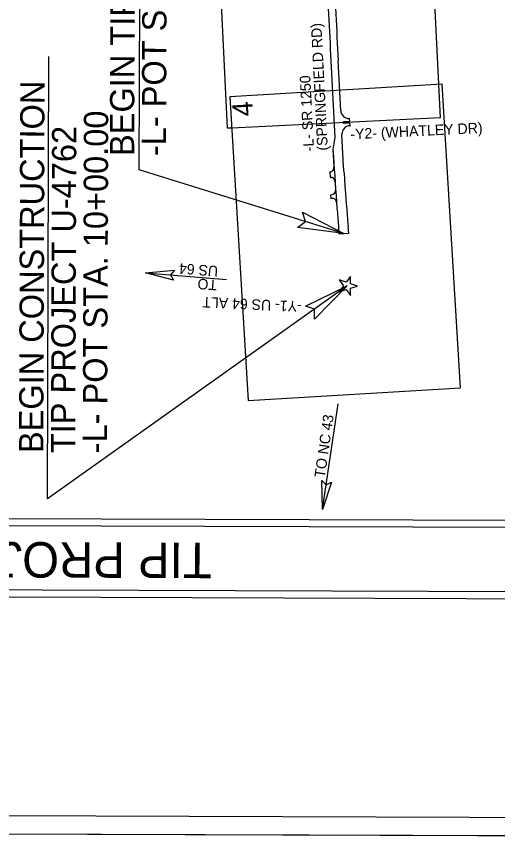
# Model space of a CAD drawing. Extents: x 2364794 to 2387902, y 795230 to 810426.
# Drawn here: x 2367330 to 2369706, y 798611 to 802661 of the extents above; entities that cross this region are included whole.
import ezdxf

# ---------------------------------------------------------------- set-up
doc = ezdxf.new("R2010")
doc.units = 0
for name, color, linetype in [('Mis Object Lines', 7, 'Continuous'), ('Old_Level_10', 7, 'Continuous'), ('Old_Level_15', 7, 'Continuous'), ('Old_Level_20', 7, 'Continuous'), ('Old_Level_21', 7, 'Continuous'), ('Old_Level_22', 7, 'Continuous'), ('Old_Level_5', 7, 'Continuous'), ('Old_Level_7', 7, 'Continuous'), ('Old_Level_8', 7, 'Continuous'), ('Plan Sheet CELL', 7, 'Continuous')]:
    doc.layers.add(name, color=color, linetype=linetype)

msp = doc.modelspace()

# ---------------------------------------------------------------- linework, layer by layer
at = {"layer": 'Mis Object Lines'}
for p, q in [((2370923.9, 800170.6), (2365078.9, 800191.3)), ((2372218.8, 800131.1), (2365078.8, 800156.3))]:
    msp.add_line(p, q, dxfattribs=at)
for points in [[(2365077.7, 799841.4), (2372217.7, 799816.1)], [(2365042.6, 799806.4), (2372252.5, 799781)], [(2365042.6, 799806.4), (2372252.5, 799781)]]:
    msp.add_lwpolyline(points, dxfattribs=at)
at = {"layer": 'Old_Level_10'}
for points in [[(2368743.3, 801694.6), (2368946.7, 801590.8), (2368718.7, 801619.8), (2368758.1, 801649.4)], [(2368106.2, 801360.1), (2367968.2, 801395.5), (2368110.9, 801409), (2368091, 801385.5)], [(2368757.7, 801232.6), (2368963.6, 801331.3), (2368802.3, 801167.7), (2368802.6, 801217)], [(2368885.9, 800364.4), (2368841.4, 800229), (2368837.4, 800372.4), (2368859.5, 800350.9)]]:
    msp.add_lwpolyline(points, close=True, dxfattribs=at)
at = {"layer": 'Old_Level_15'}
for p, q in [((2367937.1, 801904.7), (2367946.1, 804439.4)), ((2367483.3, 800281.4), (2367491, 802463.8)), ((2368946.7, 801590.8), (2367937.1, 801904.7)), ((2367968.2, 801395.5), (2368367.4, 801363.2)), ((2368963.6, 801331.3), (2367483.3, 800281.4)), ((2368841.4, 800229), (2368918.9, 800750.9))]:
    msp.add_line(p, q, dxfattribs=at)
at = {"layer": 'Old_Level_20'}
msp.add_line((2368922.7, 801589.2), (2368970.6, 801592.4), dxfattribs=at)
at = {"layer": 'Old_Level_21'}
msp.add_lwpolyline([(2364835.2, 810426.2), (2364793.5, 798638.3), (2372493.4, 798611.1), (2372535.1, 810399)], close=True, dxfattribs=at)
at = {"layer": 'Old_Level_22'}
msp.add_lwpolyline([(2372336.7, 798702.6), (2372377.9, 810368.1), (2364992.2, 810394.2), (2364951, 798728.7)], close=True, dxfattribs=at)
at = {"layer": 'Old_Level_5'}
for p, q in [((2368882.8, 802441.2), (2368902.1, 802064.1)), ((2368931.4, 802195.4), (2368918.7, 802443.1)), ((2368975.5, 802157.6), (2368973.2, 802157.5)), ((2368976.2, 802143.7), (2368975.5, 802157.6)), ((2368947.2, 802142.2), (2368976.2, 802143.7)), ((2368976.6, 802134.7), (2368947.6, 802133.4)), ((2368975.4, 802121.5), (2368977.2, 802121.6)), ((2368977.2, 802121.6), (2368976.6, 802134.7)), ((2368902.1, 802064.1), (2368893.2, 802003.6)), ((2368945.5, 801921.2), (2368937.4, 802079.5)), ((2368893.2, 802003.6), (2368897.6, 801918.7)), ((2368897.6, 801918.7), (2368897.8, 801915.9)), ((2368947.8, 801889.5), (2368945.5, 801921.2)), ((2368879.3, 801894.6), (2368878.4, 801894.5)), ((2368878.4, 801894.5), (2368879.8, 801866.8)), ((2368879.8, 801866.8), (2368881.6, 801866.9)), ((2368892.7, 801783), (2368881.4, 801779)), ((2368881.4, 801779), (2368882.5, 801761.6)), ((2368920.8, 801619), (2368922.7, 801589.2)), ((2368970.6, 801592.4), (2368968.7, 801622.5)), ((2368922.7, 801589.2), (2368970.6, 801592.4))]:
    msp.add_line(p, q, dxfattribs=at)
for centre, radius, start, end in [((2425310.1, 805339.7), 56501.7, 182.47241, 182.94048), ((2425310.1, 805339.7), 56465.7, 182.47241, 182.94048), ((2368971.4, 802197.4), 40, 182.9405, 272.6684), ((2368977.3, 802081.6), 40, 92.7637, 182.9405), ((2368947.4, 802137.8), 4.44, 92.4729, 272.8864), ((2397182.2, 803762.9), 28343.7, 183.55876, 184.08289), ((2397182.2, 803762.9), 28343.7, 183.55876, 184.08289), ((2368877.8, 801914.5), 20, 274.2541, 4.0821), ((2368882.7, 801846.9), 20, 4.1945, 93.0317), ((2377170.4, 802398.1), 8238.3, 183.53925, 185.40206), ((2388872.6, 803313), 20023.6, 184.19448, 184.32363), ((2368886, 801801.9), 20, 289.4241, 4.3236), ((2368890.6, 801743.3), 20, 4.4915, 113.8787), ((2388872.6, 803313), 20023.6, 184.49152, 184.60953), ((2388872.6, 803313), 20023.6, 184.60953, 184.85295)]:
    msp.add_arc(centre, radius, start, end, dxfattribs=at)
at = {"layer": 'Old_Level_7'}
for points in [[(2368394, 802110), (2368373.1, 802109), (2368300, 803607.2), (2369348.7, 803658.4), (2369413.8, 802325.9)], [(2369413.8, 802325.9), (2369421.9, 802160.1), (2368394, 802110)]]:
    msp.add_lwpolyline(points, dxfattribs=at)
msp.add_lwpolyline([(2368474.8, 800766.7), (2369522.9, 800829.7), (2369432.8, 802327), (2368384.7, 802264)], close=True, dxfattribs=at)
at = {"layer": 'Old_Level_8'}
msp.add_lwpolyline([(2368979, 801342.5), (2368979.2, 801378.8), (2368957.8, 801349.5), (2368923.2, 801360.9), (2368944.5, 801331.4), (2368923, 801302.1), (2368957.6, 801313.2), (2368978.9, 801283.8), (2368979, 801320.1), (2369013.6, 801331.2), (2368979, 801342.5)], dxfattribs=at)
at = {"layer": 'Plan Sheet CELL'}
msp.add_line((2364793.5, 798638.3), (2372493.4, 798611.1), dxfattribs=at)

# ---------------------------------------------------------------- texts
at = {"layer": 'Mis Object Lines'}
msp.add_text('TIP PROJECT:', height=175, rotation=179.7976, dxfattribs=at).set_placement((2368295.1, 800065.2))
at = {"layer": 'Old_Level_15'}
for s, height, rotation, p in [('BEGIN TIP PROJECT U-4762', 120, 89.7976, (2367911.6, 801972.3)), ('-L- POT STA. 12+60.00', 120, 89.7976, (2368068.9, 801971.7)), ('(SPRINGFIELD RD)', 52, 92.9405, (2368868, 802000.3)), ('-L- SR 1250 ', 52, 92.9405, (2368799.9, 801996.8)), ('BEGIN CONSTRUCTION ', 120, 89.7976, (2367463.1, 800507.1)), ('4', 100, 93.443, (2368498.9, 802170.2)), ('-L- POT STA. 10+00.00', 120, 89.7976, (2367777.8, 800506)), ('TIP PROJECT U-4762', 120, 89.7976, (2367620.5, 800506.6)), ('-Y2- (WHATLEY DR)', 52, 2.7943, (2368980.4, 802054.2)), ('US 64', 52, 175.6717, (2368327.8, 801429.2)), ('TO ', 52, 175.6717, (2368322.7, 801361.2)), ('-Y1- US 64 ALT', 52, 177.2651, (2368739.9, 801254.6)), ('TO NC 43', 52, 81.839, (2368852.7, 800383.4))]:
    msp.add_text(s, height=height, rotation=rotation, dxfattribs=at).set_placement(p)

doc.saveas('drawing.dxf')
